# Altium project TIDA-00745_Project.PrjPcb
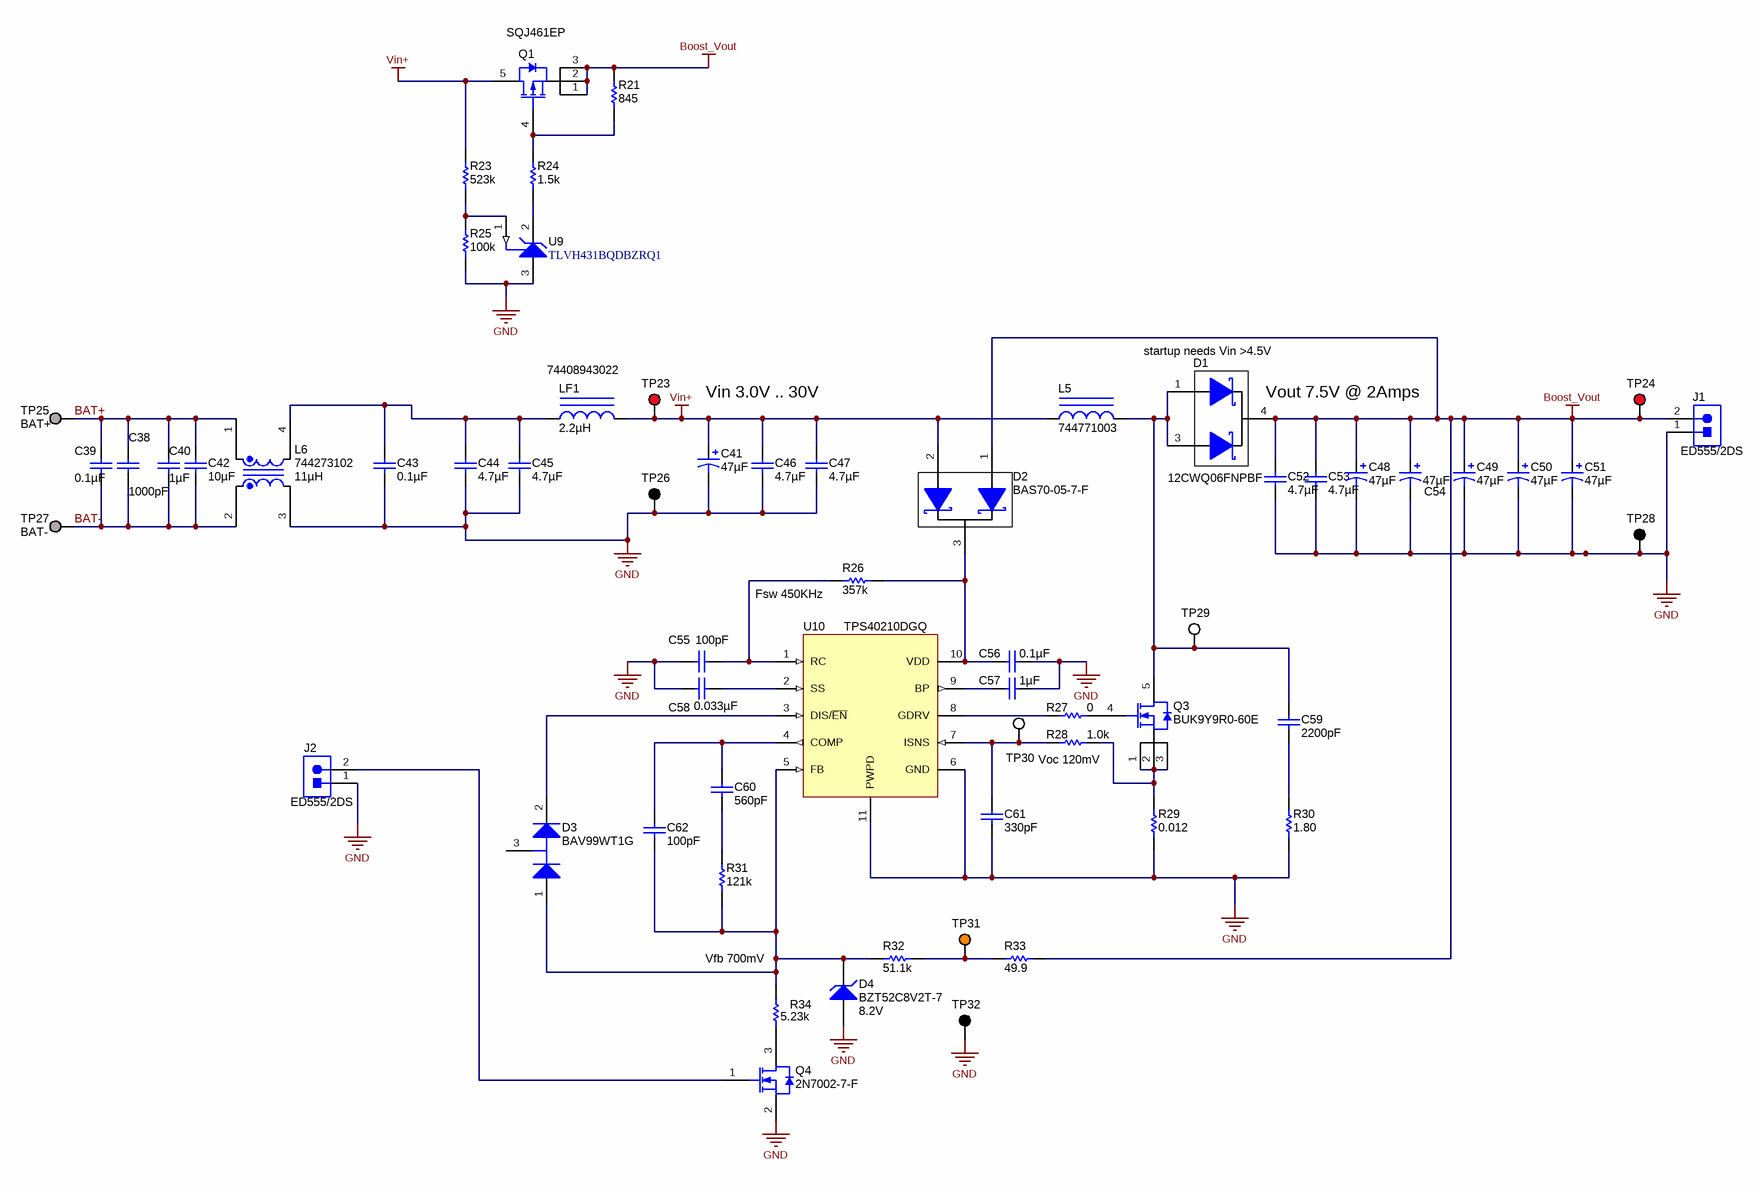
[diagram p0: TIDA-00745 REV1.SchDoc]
TechSupport: http://www.ti.com/support; SCH_Rev: E1; PRJ_Title: SMPS design for Automotive Body Contrl Module; PRJ_Number: TIDA-00745; PRJ_Engineer: Ambreesh Tripathi; PRJ_Customer: Public Release; PCB_Rev: E1; PCB_Layout: Dee Lim; CopyrightYear: 2015
3 sheets, 180 parts. Net scope: global (net labels, ports and power ports of the same name join across sheets).
Board file: TIDA-00745_PCB.PcbDoc
Sheets:
  TIDA-00745 REV1.SchDoc
  TIDA-00745_Hardware.SchDoc
  TIDA-00745_Buck REV1.SchDoc

## Sheet TIDA-00745 REV1.SchDoc
size 431 x 279 mm; Date: Not shown in title block; ApprovedBy: Not shown in title block; CheckedBy: Not shown in title block; Author: Not shown in title block; CompanyName: Not shown in title block; Engineer: Not shown in title block; Organization: Not shown in title block; Address1: Not shown in title block; Address2: Not shown in title block; Address3: Not shown in title block; Address4: Not shown in title block; DocumentNumber: 1; Revision: Use project parameter SCH_Rev; SheetNumber: 2; SheetTotal: 1; PageSetup: Record=PageOptions|CenterHorizontal=True|CenterVertical=True|PrintScale=0.64|XCorrection=1.00|YCorrection=1.00|PrintKind=0|BorderSize=5000000|LeftOffset=0|BottomOffset=0|Orientation=2|PaperLength=1000|PaperWidth=1000|Scale=100|PaperSource=15|PrintQuality=-3|MediaType=1|DitherType=10|PrintScaleMode=1|PaperKind=Tabloid (11 x 17")|PaperIndex=17

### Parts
C38  ValueDisplayed: 1000pF  [0603]  (hidden comment: 06031C102KAT2A)
C39  ValueDisplayed: 0.1µF  [0603]  (hidden comment: GRM188R72A104KA35D)
C40  ValueDisplayed: 1µF  [1206]  (hidden comment: C3216X7R2A105M160AA)
C41  ValueDisplayed: 47µF  [SM_RADIAL_G]  (hidden comment: EEE-FC1H470P)
C42  ValueDisplayed: 10µF  [1210]  (hidden comment: GRM32ER71H106KA12L)
C43  ValueDisplayed: 0.1µF  [0603]  (hidden comment: C1608X7R1H104K)
C44  ValueDisplayed: 4.7µF  [1206]  (hidden comment: GRM31CR71H475KA12L)
C45  ValueDisplayed: 4.7µF  [1206]  (hidden comment: GRM31CR71H475KA12L)
C46  ValueDisplayed: 4.7µF  [1210]  (hidden comment: GRM32ER71H475KA88L)
C47  ValueDisplayed: 4.7µF  [1210]  (hidden comment: GRM32ER71H475KA88L)
C48  ValueDisplayed: 47µF  [SM_RADIAL_G]  (hidden comment: EEE-FC1H470P)
C49  ValueDisplayed: 47µF  [SM_RADIAL_G]  (hidden comment: EEE-FC1H470P)
C50  ValueDisplayed: 47µF  [SM_RADIAL_G]  (hidden comment: EEE-FC1H470P)
C51  ValueDisplayed: 47µF  [SM_RADIAL_G]  (hidden comment: EEE-FC1H470P)
C52  ValueDisplayed: 4.7µF  [1210]  (hidden comment: GRM32ER71H475KA88L)
C53  ValueDisplayed: 4.7µF  [1210]  (hidden comment: GRM32ER71H475KA88L)
C54  ValueDisplayed: 47µF  [SM_RADIAL_G]  (hidden comment: EEE-FC1H470P)
C55  ValueDisplayed: 100pF  [0603]  (hidden comment: 06035A101JAT2A)
C56  ValueDisplayed: 0.1µF  [0603]  (hidden comment: GRM188R71H104KA93D)
C57  ValueDisplayed: 1µF  [0603]  (hidden comment: GRM188R71E105KA12D)
C58  ValueDisplayed: 0.033µF  [0603]  (hidden comment: GRM188R71H333KA61D)
C59  ValueDisplayed: 2200pF  [0603]  (hidden comment: GRM188R71E222KA01D)
C60  ValueDisplayed: 560pF  [0603]  (hidden comment: C0603C561K5RACTU)
C61  ValueDisplayed: 330pF  [0603]  (hidden comment: GRM188R71H331KA01D)
C62  ValueDisplayed: 100pF  [0603]  (hidden comment: 06035A101JAT2A)
D1  12CWQ06FNPBF  [DPAK]
D2  BAS70-05-7-F  [SOT-23]
D3  BAV99WT1G  [SOT-323]
D4  BZT52C8V2T-7  value 8.2V  [SOD-523]
J1  ED555/2DS  [TERM_BLK_ED555-2DS]
J2  ED555/2DS  [TERM_BLK_ED555-2DS]
L5  744771003  [WE-PD-L]
L6  744273102  ValueDisplayed: 11µH  [WE-SL5_HC]
LF1  74408943022  ValueDisplayed: 2.2µH  [WE-SPC_4838]
Q1  SQJ461EP  [PowerPAK_SO-8L]
Q3  BUK9Y9R0-60E  [LFPAK56]
Q4  2N7002-7-F  [SOT-23]
R21  ValueDisplayed: 845  [0603]  (hidden comment: CRCW0603845RFKEA)
R23  ValueDisplayed: 523k  [0603]  (hidden comment: CRCW0603523KFKEA)
R24  ValueDisplayed: 1.5k  [0603]  (hidden comment: CRCW06031K50JNEA)
R25  ValueDisplayed: 100k  [0603]  (hidden comment: CRCW0603100KFKEA)
R26  ValueDisplayed: 357k  [0603]  (hidden comment: RC0603FR-07357KL)
R27  value 0  [0603]  (hidden comment: CRCW06030000Z0EA)
R28  value 1.0k  [0603]  (hidden comment: CRCW06031K00JNEA)
R29  ValueDisplayed: 0.012  [1206]  (hidden comment: CSR1206FK12L0)
R30  value 1.80  [1206]  (hidden comment: RC1206FR-071R8L)
R31  ValueDisplayed: 121k  [0603]  (hidden comment: CRCW0603121KFKEA)
R32  ValueDisplayed: 51.1k  [0603]  (hidden comment: CRCW060351K1FKEA)
R33  value 49.9  [0603]  (hidden comment: CRCW060349R9FKEA)
R34  ValueDisplayed: 5.23k  [0603]  (hidden comment: CRCW06035K23FKEA)
TP23  5000  [Keystone5000]  (value not drawn)
TP24  5000  [Keystone5000]  (value not drawn)
TP25  BAT+  [Keystone1503-2]
TP26  5001  [Keystone5001]  (value not drawn)
TP27  BAT-  [Keystone1503-2]
TP28  5001  [Keystone5001]  (value not drawn)
TP29  5002  [Keystone5002]  (value not drawn)
TP30  5002  [Keystone5002]  (value not drawn)
TP31  5003  [Keystone5003]  (value not drawn)
TP32  5001  [Keystone5001]  (value not drawn)
U9  TLVH431BQDBZRQ1  [DBZ0003A_N]
U10  TPS40210DGQ  [DGQ0010D_N]

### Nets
Boost_Vout: C48.1(+) C49.1(+) C50.1(+) C51.1(+) C52.1 C53.1 C54.1(+) D1.4(K) D2.1(A) J1.2 Q1.1(S) Q1.2(S) Q1.3(S) R21.2 R33.2 TP24.1  [project net Vs]
GND: C41.2(-) C43.2 C44.2 C45.2 C46.2 C47.2 C48.2(-) C49.2(-) C50.2(-) C51.2(-) C52.2 C53.2 C54.2(-) C55.1 C56.2 C57.2 C58.2 C61.2 D4.2(A) J1.1 J2.1 L6.3 Q4.2(S) R25.1 R29.1 R30.1 TP26.1 TP28.1 TP32.1 U9.3(ANODE) U10.6(GND) U10.11(PWPD)
Vin+: C41.1(+) C46.1 C47.1 D2.2(A) L5.1 LF1.2 Q1.5(D) R23.2 TP23.1
BAT+: C38.1 C39.1 C40.1 C42.1 L6.1 TP25.1
BAT-: C38.2 C39.2 C40.2 C42.2 L6.2 TP27.1
NetC43_1: C43.1 C44.1 C45.1 L6.4 LF1.1
NetC55_2: C55.2 R26.1 U10.1(RC)
NetC56_1: C56.1 D2.3(K) R26.2 U10.10(VDD)
NetC57_1: C57.1 U10.9(BP)
NetC58_1: C58.1 U10.2(SS)
NetC59_1: C59.1 D1.1(A) D1.3(A) L5.2 Q3.5(D) TP29.1
NetC59_2: C59.2 R30.2
NetC60_1: C60.1 C62.2 U10.4(COMP)
NetC60_2: C60.2 R31.2
NetC61_1: C61.1 R28.1 TP30.1 U10.7(ISNS)
NetC62_1: C62.1 D3.1(A) D4.1(K) R31.1 R32.1 R34.2 U10.5(FB)
NetD3_2: D3.2(K) U10.3(DIS/~{EN})
NetJ2_2: J2.2 Q4.1(G)
NetQ1_4: Q1.4(G) R21.1 R24.2
NetQ3_1: Q3.1(S) Q3.2(S) Q3.3(S) R28.2 R29.2
NetQ3_4: Q3.4(G) R27.2
NetQ4_3: Q4.3(D) R34.1
NetR23_1: R23.1 R25.2 U9.1(REF)
NetR24_1: R24.1 U9.2(CATHODE)
NetR27_1: R27.1 U10.8(GDRV)
NetR32_2: R32.2 R33.1 TP31.1

Not connected (* = marked no-connect by the designer): D3 3(C)

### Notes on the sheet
- (near D1) startup needs Vin >4.5V
- Vin 3.0V .. 30V
- (near D1) Vout 7.5V @ 2Amps
- (near R26) Fsw 450KHz
- (near R28) Voc 120mV
- (near R34) Vfb 700mV

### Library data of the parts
C38 = 06031C102KAT2A: CAP, CERM, 1000 pF, 100 V, +/- 10%, X7R, 0603; Manufacturer: AVX; Polarized: N; CompType: Capacitor; Value: 1000pF; U/M: EA; Cap_F: 0.000000001; Tolerance_%: 10; ESR_ohm: 0.276; Value1: 0.276 ohm; VDC_V: 100; Value2: 100V; TaMin_C: -55; TaMax_C: 125
C39 = GRM188R72A104KA35D: CAP, CERM, 0.1uF, 100V, +/-10%, X7R, 0603; Manufacturer: MuRata; Polarized: N; CompType: Capacitor; U/M: EA; Cap_F: 0.0000001; Tolerance_%: 10; Value1: Unknown; VDC_V: 100; TaMin_C: -55; TaMax_C: 125
C40 = C3216X7R2A105M160AA: CAP, CERM, 1uF, 100V, +/-20%, X7R, 1206; Manufacturer: TDK; Polarized: N; CompType: Capacitor; U/M: EA; Cap_F: 0.000001; Tolerance_%: 20; Value1: Unknown; VDC_V: 100; TaMin_C: -55; TaMax_C: 125
C41 C48-C51 C54 = EEE-FC1H470P: CAP, AL, 47 µF, 50 V, +/- 20%, 0.3 ohm, SMD; Manufacturer: Panasonic; Polarized: Y; CompType: Capacitor; Value: 47uF; U/M: EA; Cap_F: 0.000047; Tolerance_%: 20; Value1: 0.3 ohm; VDC_V: 50; Value2: 50V; ESR_ohm: 0.3; IRMS_A: 0.5; TaMin_C: -40; TaMax_C: 105; Cap_Case: G
C42 = GRM32ER71H106KA12L: CAP, CERM, 10uF, 50V, +/-10%, X7R, 1210; Manufacturer: MuRata; Polarized: N; CompType: Capacitor; U/M: EA; Cap_F: 0.00001; Tolerance_%: 10; Value1: Unknown; VDC_V: 50; TaMin_C: -55; TaMax_C: 125
C43 = C1608X7R1H104K: CAP, CERM, 0.1uF, 50V, +/-10%, X7R, 0603; Manufacturer: TDK; Polarized: N; CompType: Capacitor; U/M: EA; Cap_F: 0.0000001; Tolerance_%: 10; ESR_Ohm: 0.017; Value1: 0.017 ohm; VDC_V: 50; TaMin_C: -55; TaMax_C: 125
C44 C45 = GRM31CR71H475KA12L: CAP, CERM, 4.7uF, 50V, +/-10%, X7R, 1206; Manufacturer: MuRata; Polarized: N; CompType: Capacitor; U/M: EA; Cap_F: 0.0000047; Tolerance_%: 10; Value1: Unknown; VDC_V: 50; TaMin_C: -55; TaMax_C: 125; Cap_Case: 2220
C46 C47 C52 C53 = GRM32ER71H475KA88L: CAP, CERM, 4.7 µF, 50 V, +/- 10%, X7R, 1210; Manufacturer: MuRata; Polarized: N; CompType: Capacitor; Value: 4.7uF; U/M: EA; Cap_F: 0.0000047; Tolerance_%: 10; ESR_ohm: 0.002; Value1: 0.002 ohm; VDC_V: 50; Value2: 50V; TaMin_C: -55; TaMax_C: 125
C55 C62 = 06035A101JAT2A: CAP, CERM, 100 pF, 50 V, +/- 5%, C0G/NP0, 0603; Manufacturer: AVX; Polarized: N; CompType: Capacitor; Value: 100pF; U/M: EA; Cap_F: 0.0000000001; Tolerance_%: 5; ESR_ohm: 0.119; Value1: 0.119 ohm; VDC_V: 50; Value2: 50V; TaMin_C: -55; TaMax_C: 125; AEC Category: Q200
C56 = GRM188R71H104KA93D: CAP, CERM, 0.1uF, 50V, +/-10%, X7R, 0603; Manufacturer: MuRata; Polarized: N; CompType: Capacitor; U/M: EA; Cap_F: 0.0000001; Tolerance_%: 10; Value1: Unknown; VDC_V: 50; TaMin_C: -55; TaMax_C: 125
C57 = GRM188R71E105KA12D: CAP, CERM, 1uF, 25V, +/-10%, X7R, 0603; Manufacturer: MuRata; Polarized: N; CompType: Capacitor; U/M: EA; Cap_F: 0.000001; Tolerance_%: 10; Value1: Unknown; VDC_V: 25; TaMin_C: -55; TaMax_C: 125
C58 = GRM188R71H333KA61D: CAP, CERM, 0.033 µF, 50 V, +/- 10%, X7R, 0603; Manufacturer: MuRata; Polarized: N; CompType: Capacitor; Value: 0.033uF; U/M: EA; Cap_F: 0.000000033; Tolerance_%: 10; Value1: Unknown; VDC_V: 50; Value2: 50V; TaMin_C: -55; TaMax_C: 125
C59 = GRM188R71E222KA01D: CAP, CERM, 2200pF, 25V, +/-10%, X7R, 0603; Manufacturer: MuRata; Polarized: N; CompType: Capacitor; U/M: EA; Cap_F: 0.0000000022; Tolerance_%: 10; Value1: Unknown; VDC_V: 25; TaMin_C: -55; TaMax_C: 125
C60 = C0603C561K5RACTU: CAP, CERM, 560 pF, 50 V, +/- 10%, X7R, 0603; Manufacturer: Kemet; Polarized: N; CompType: Capacitor; Value: 560pF; U/M: EA; Cap_F: 0.00000000056; Tolerance_%: 10; Value1: Unknown; VDC_V: 50; Value2: 50V; TaMin_C: -55; TaMax_C: 125
C61 = GRM188R71H331KA01D: CAP, CERM, 330pF, 50V, +/-10%, X7R, 0603; Manufacturer: MuRata; Polarized: N; CompType: Capacitor; U/M: EA; Cap_F: 0.00000000033; Tolerance_%: 10; Value1: Unknown; VDC_V: 50; TaMin_C: -55; TaMax_C: 125
D1 = 12CWQ06FNPBF: Diode, Schottky, 60 V, 12 A, DPAK; Manufacturer: Vishay-Semiconductor; U/M: EA; Vf_V: 0.79; Value: 60V; Value1: 12A; Value2: 0.79V; Io_A: 12; Vr_V: 60; TJmax_C: 150; RJC_CperW: 1.5
D2 = BAS70-05-7-F: Diode, Schottky, 70 V, 0.07 A, SOT-23; Manufacturer: Diodes Inc.; SymbolCreator: a0412235; U/M: EA; Vf_V: 1.7; Value: 70V; Value1: 0.07A; Value2: 1.7V; Io_A: 0.07; Vr_V: 70
D3 = BAV99WT1G: Diode, P-N, 70 V, 0.2 A, SOT-323; Manufacturer: Fairchild Semiconductor; U/M: EA; Vf_V: 0.63; Value: 70V; Value1: 0.2A; Value2: 0.63V; Io_A: 0.2; Vr_V: 70; TJmax_C: 150
D4 = BZT52C8V2T-7: Diode, Zener, 8.2 V, 300 mW, SOD-523; Manufacturer: Diodes Inc.; SymbolCreator: a0412235; U/M: EA; Power_W: 0.3; Vz_V: 8.2; Value1: 0.3W; RJA_CperW: 417
J1 J2 = ED555/2DS: Terminal Block, 6A, 3.5mm Pitch, 2-Pos, TH; Manufacturer: On-Shore Technology; SymbolCreator: a0412235; CompType: Connector; U/M: EA
L5 = 744771003: Inductor, Shielded Drum Core, Ferrite, 3.5 µH, 9 A, 0.005 ohm, SMD; Manufacturer: Wurth Elektronik; Value: 3.5uH; Ind_H: 3.5E-6; ValueDisplayed: 3.5µH; Imax_A: 9; Irms: 9.25A @ 40C rise; Isat: 9A @ 10% inductance drop; DCR_ohm: 0.005; Value2: 9A
L6 = 744273102: Coupled inductor, 11 µH, 2.5 A, 0.03 ohm, SMD; Manufacturer: Wurth Elektronik eiSos; SymbolCreator: a0799628; Ind_H: 11.0E-6; DCR_ohm: 0.03; Isat: 2.5; Value: 11uH
LF1 = 74408943022: Inductor, Shielded Drum Core, Ferrite, 2.2 µH, 3 A, 0.026 ohm, SMD; Manufacturer: Wurth Elektronik; Value: 2.2uH; Ind_H: 2.2E-6; Imax_A: 3; Irms: 3A @ 40C rise; Isat: 4.6A @ 35% inductance drop; DCR_ohm: 0.026; Value2: 3A; AEC Category: Q200
Q1 = SQJ461EP: MOSFET, P-CH, -60 V, 30 A, PowerPAK_SO-8L; Manufacturer: Vishay-Siliconix; Alternate Manufacturer: None; SymbolCreator: a0411947; U/M: EA; ChType: P; Value: -60V; Value1: 0.031 ohm; Rdson45_ohm: 0.031; Value2: 90 nC; QgTyp_nC: 90; Vgs_V: 20; IdsMax_A: 30
Q3 = BUK9Y3R5-40E,115: MOSFET, N-CH, 60 V, 100 A, SOT669; Manufacturer: NXP Semiconductor; Alternate Manufacturer: None; SymbolCreator: a0412235; U/M: EA; ChType: N; Value: 40V; VdsMax_V: 40; Value1: ? ohm; Value2: 30.2 nC; QgTyp_nC: 30.2; Vgs_V: 10; IdsMax_A: 100
Q4 = 2N7002-7-F: MOSFET, N-CH, 60 V, 0.17 A, SOT-23; Manufacturer: Diodes Inc.; Alternate Manufacturer: None; U/M: EA; ChType: N; Value: 60V; VdsMax_V: 60; Value1: 7.5 ohm; Rdson45_ohm: 7.5; Value2: 223 nC; QgTyp_nC: 223; Vgs_V: 20; IdsMax_A: 0.17
R21 = CRCW0603845RFKEA: RES, 845, 1%, 0.1 W, 0603; Manufacturer: Vishay-Dale; CompType: Resistor; Value: 845; Value_Code: 845R; Tolerance_%: 1; Power_W: 0.1; Value2: 0.1W; VDC_V: 75; TempCo: 100 ppm/C; EIA_Code: E96; U/M: EA
R23 = CRCW0603523KFKEA: RES, 523 k, 1%, 0.1 W, 0603; Manufacturer: Vishay-Dale; CompType: Resistor; Value: 523k; Res_ohm: 523000; Tolerance_%: 1; Power_W: 0.1; Value2: 0.1W; VDC_V: 75; TempCo: 100 ppm/C; EIA_Code: E96; U/M: EA
R24 = CRCW06031K50JNEA: RES, 1.5 k, 5%, 0.1 W, 0603; Manufacturer: Vishay-Dale; CompType: Resistor; Value: 1.5k; Res_ohm: 1500; Value_Code: 1k50; Tolerance_%: 5; Power_W: 0.1; Value2: 0.1W; VDC_V: 75; TempCo: 200 ppm/C; EIA_Code: E24; U/M: EA
R25 = CRCW0603100KFKEA: RES, 100 k, 1%, 0.1 W, 0603; Manufacturer: Vishay-Dale; CompType: Resistor; Value: 100k; Res_ohm: 100000; Tolerance_%: 1; Power_W: 0.1; Value2: 0.1W; VDC_V: 75; TempCo: 100 ppm/C; EIA_Code: E96; U/M: EA
R26 = RC0603FR-07357KL: RES, 357 k, 1%, 0.1 W, 0603; Manufacturer: Yageo America; CompType: Resistor; Value: 357k; Res_ohm: 357000; Tolerance_%: 1; Power_W: 0.1; Value2: 0.1W; VDC_V: 150; TempCo: 200 ppm/C; EIA_Code: E96; U/M: EA
R27 = CRCW06030000Z0EA: RES, 0 ohm, 5%, 0.1W, 0603; Manufacturer: Vishay-Dale; CompType: Resistor; Value_Code: 0000; Tolerance_%: 5; Power_W: 0.1; VDC_V: 75; TempCo: 200 ppm/C; EIA_Code: E24; U/M: EA
R28 = CRCW06031K00JNEA: RES, 1.0k ohm, 5%, 0.1W, 0603; Manufacturer: Vishay-Dale; CompType: Resistor; Res_ohm: 1000; Value_Code: 1k00; Tolerance_%: 5; Power_W: 0.1; VDC_V: 75; TempCo: 200 ppm/C; EIA_Code: E24; U/M: EA
R29 = CSR1206FK12L0: RES, 0.012, 1%, 0.5 W, 1206; Manufacturer: Stackpole Electronics Inc; CompType: Resistor; Value: 0.012; Value_Code: R012; Tolerance_%: 1; Power_W: 0.5; Value2: 0.5W; TempCo: 100 ppm/C; EIA_Code: E96; U/M: EA
R30 = RC1206FR-071R8L: RES, 1.80 ohm, 1%, 0.25W, 1206; Manufacturer: Yageo America; CompType: Resistor; Res_ohm: 1.8; Value_Code: 1R80; Tolerance_%: 1; Power_W: 0.25; VDC_V: 200; TempCo: 200 ppm/C; U/M: EA
R31 = CRCW0603121KFKEA: RES, 121 k, 1%, 0.1 W, 0603; Manufacturer: Vishay-Dale; CompType: Resistor; Value: 121k; Res_ohm: 121000; Tolerance_%: 1; Power_W: 0.1; Value2: 0.1W; VDC_V: 75; TempCo: 100 ppm/C; EIA_Code: E96; U/M: EA
R32 = CRCW060351K1FKEA: RES, 51.1 k, 1%, 0.1 W, 0603; Manufacturer: Vishay-Dale; CompType: Resistor; Value: 51.1k; Res_ohm: 51100; Value_Code: 51k1; Tolerance_%: 1; Power_W: 0.1; Value2: 0.1W; VDC_V: 75; TempCo: 100 ppm/C; EIA_Code: E96; U/M: EA
R33 = CRCW060349R9FKEA: RES, 49.9 ohm, 1%, 0.1W, 0603; Manufacturer: Vishay-Dale; CompType: Resistor; Value_Code: 49R9; Tolerance_%: 1; Power_W: 0.1; VDC_V: 75; TempCo: 100 ppm/C; EIA_Code: E96; U/M: EA
R34 = CRCW06035K23FKEA: RES, 5.23 k, 1%, 0.1 W, 0603; Manufacturer: Vishay-Dale; CompType: Resistor; Value: 5.23k; Res_ohm: 5230; Value_Code: 5k23; Tolerance_%: 1; Power_W: 0.1; Value2: 0.1W; VDC_V: 75; TempCo: 100 ppm/C; EIA_Code: E96; U/M: EA
TP23 TP24 = 5000: Test Point, Miniature, Red, TH; Manufacturer: Keystone; CompType: Test Point Loop; U/M: EA
TP25 TP27 = 1503-2: Terminal, Turret, TH, Double; Manufacturer: Keystone; CompType: Turret Terminal; U/M: EA
TP26 TP28 TP32 = 5001: Test Point, Miniature, Black, TH; Manufacturer: Keystone; CompType: Test Point Loop; U/M: EA
TP29 TP30 = 5002: Test Point, Miniature, White, TH; Manufacturer: Keystone; CompType: Test Point Loop; U/M: EA
TP31 = 5003: Test Point, Miniature, Orange, TH; Manufacturer: Keystone; CompType: Test Point Loop; U/M: EA
U9 = TLVH431BQDBZRQ1: Automotive Catalog Low-Voltage Adjustable Precision Shunt Regulator, 80 mA, -40 to 125 degC, 3-pin SOT-23 (DBZ), Green (RoHS & no Sb/Br); Manufacturer: Texas Instruments; Alternate PartNumber: Equivalent; Initial Accuracy @ 25/deg C(%): 0.5; Iout/Iz(Max)(mA): 80; SubFamily: Shunt Voltage Reference; VO Adj(Max)(V): 18; VO Adj(Min)(V): 1.24
U10 = TPS40210DGQ: 4.5-V TO 52-V INPUT CURRENT MODE BOOST CONTROLLER, DGQ0010D; Alternate Manufacturer: None; Manufacturer: Texas Instruments; SymbolCreator: a0412235; CompType: IC; U/M: EA

## Sheet TIDA-00745_Hardware.SchDoc
size 431 x 279 mm; Date: Not shown in title block; ApprovedBy: Not shown in title block; CheckedBy: Not shown in title block; Author: Not shown in title block; CompanyName: Not shown in title block; Engineer: Not shown in title block; Organization: Not shown in title block; Address1: Not shown in title block; Address2: Not shown in title block; Address3: Not shown in title block; Address4: Not shown in title block; DocumentNumber: 1; Revision: Use project parameter SCH_Rev; SheetNumber: 4; SheetTotal: 1; PageSetup: Record=PageOptions¦CenterHorizontal=True¦CenterVertical=True¦PrintScale=1.00¦XCorrection=1.00¦YCorrection=1.00¦PrintKind=0¦BorderSize=5000000¦LeftOffset=0¦BottomOffset=0¦Orientation=2¦PaperLength=1000¦PaperWidth=1000¦Scale=100¦PaperSource=15¦PrintQuality=600¦MediaType=1¦DitherType=10¦PaperKind=Letter¦PrintScaleMode=1
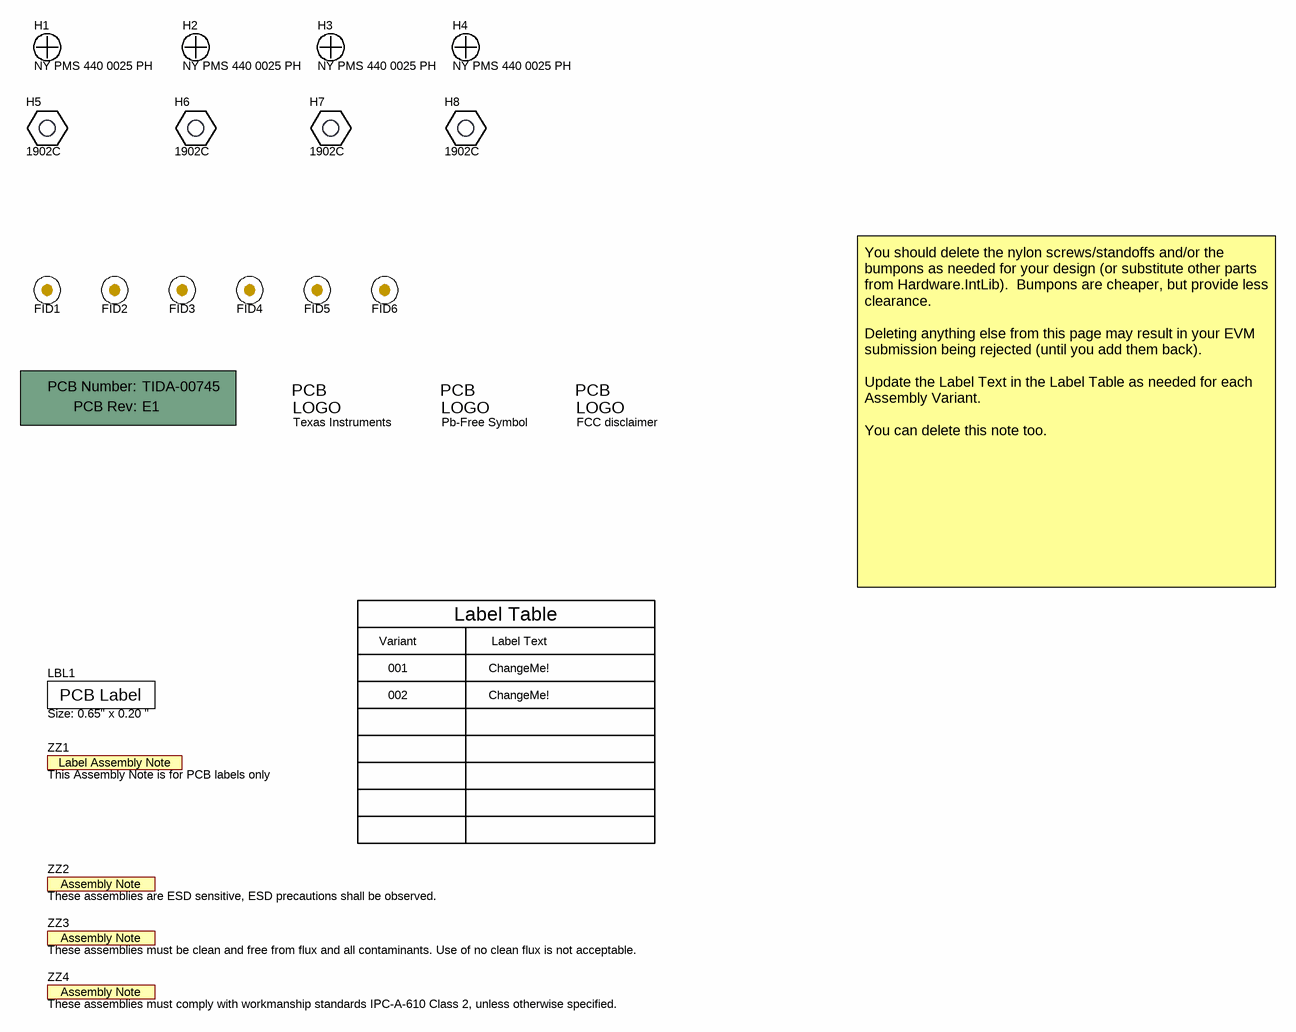
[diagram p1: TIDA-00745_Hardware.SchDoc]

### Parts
!PCB1  Printed Circuit Board  (value not drawn)  (mechanical)
FID1  Fiducial  [Fiducial10-20]  (value not drawn)
FID2  Fiducial  [Fiducial10-20]  (value not drawn)
FID3  Fiducial  [Fiducial10-20]  (value not drawn)
FID4  Fiducial  [Fiducial10-20]  (value not drawn)
FID5  Fiducial  [Fiducial10-20]  (value not drawn)
FID6  Fiducial  [Fiducial10-20]  (value not drawn)
H1  NY PMS 440 0025 PH  [NY PMS 440 0025 PH]
H2  NY PMS 440 0025 PH  [NY PMS 440 0025 PH]
H3  NY PMS 440 0025 PH  [NY PMS 440 0025 PH]
H4  NY PMS 440 0025 PH  [NY PMS 440 0025 PH]
H5  1902C  [Keystone_1902C]
H6  1902C  [Keystone_1902C]
H7  1902C  [Keystone_1902C]
H8  1902C  [Keystone_1902C]
LBL1  Size: 0.65" x 0.20 "  [Label_650x200]
Logo1  Texas Instruments  [TI_Horizontal_Overlay_Medium]  (no BOM)
Logo2  Pb-Free Symbol  [Pb-Free_Overlay_Small]  (no BOM)
Logo3  FCC disclaimer  [FCC_disclaimer]  (no BOM)
ZZ1  This Assembly Note is for PCB labels only  [AssemblyNoteLabel]  (no BOM)
ZZ2  These assemblies are ESD sensitive, ESD precautions shall be observed.  [AssemblyNote]  (no BOM)
ZZ3  These assemblies must be clean and free from flux and all contaminants. Use of no clean flux is not acceptable.  [AssemblyNote]  (no BOM)
ZZ4  These assemblies must comply with workmanship standards IPC-A-610 Class 2, unless otherwise specified.  [AssemblyNote]  (no BOM)

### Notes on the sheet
- Variant
- Label Table
- Label Text
- You should delete the nylon screws/standoffs and/or the bumpons as needed for your design (or substitute other parts from Hardware.IntLib).  Bumpons are cheaper, but provide less clearance.
  Deleting anything else from this page may result in your EVM submission being rejected (until you add them back).
  Update the Label Text in the Label Table as needed for each Assembly Variant.
  You can delete this note too.
- 001
- 002
- ChangeMe!

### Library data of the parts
!PCB1 = PCB: Manufacturer: Any; PartNumber: TIDA-00745; SymbolCreator: a0412235
FID1-FID6 = Fiducial: Fiducial mark.  There is nothing to buy or mount.; SymbolCreator: codlsc
H1-H4 = NY PMS 440 0025 PH: Machine Screw, Round, #4-40 x 1/4, Nylon, Philips panhead; Manufacturer: B&F Fastener Supply; CompType: Hardware; SymbolCreator: codlsc; U/M: EA
H5-H8 = 1902C: Standoff, Hex, 0.5"L #4-40 Nylon; Manufacturer: Keystone; CompType: Hardware; SymbolCreator: a0412235
LBL1 = THT-14-423-10: Thermal Transfer Printable Labels, 0.650" W x 0.200" H - 10,000 per roll; Manufacturer: Brady; SymbolCreator: a0412235; CompType: Label
Logo1 = TI_Logo: Texas Instrument Corporate Signature; SymbolCreator: a0412235
Logo2 = Pb-Free: SymbolCreator: a0412235
Logo3 = FCC_disclaimer: SymbolCreator: codlsc
ZZ1 = AssemblyNoteLabel: SymbolCreator: a0412235
ZZ2-ZZ4 = AssemblyNote: SymbolCreator: codlsc

## Sheet TIDA-00745_Buck REV1.SchDoc
size 431 x 279 mm; Date: Not shown in title block; ApprovedBy: Not shown in title block; CheckedBy: Not shown in title block; Author: Not shown in title block; CompanyName: Not shown in title block; Engineer: Not shown in title block; Organization: Not shown in title block; Address1: Not shown in title block; Address2: Not shown in title block; Address3: Not shown in title block; Address4: Not shown in title block; DocumentNumber: 1; Revision: Use project parameter SCH_Rev; SheetNumber: 3; SheetTotal: 1; PageSetup: Record=PageOptions¦CenterHorizontal=True¦CenterVertical=True¦PrintScale=0.96¦XCorrection=1.00¦YCorrection=1.00¦PrintKind=0¦BorderSize=5000000¦LeftOffset=0¦BottomOffset=0¦Orientation=2¦PaperLength=1000¦PaperWidth=1000¦Scale=100¦PaperSource=15¦PrintQuality=-3¦MediaType=1¦DitherType=10¦PrintScaleMode=1¦PaperKind=Tabloid (11 x 17")¦PaperIndex=17
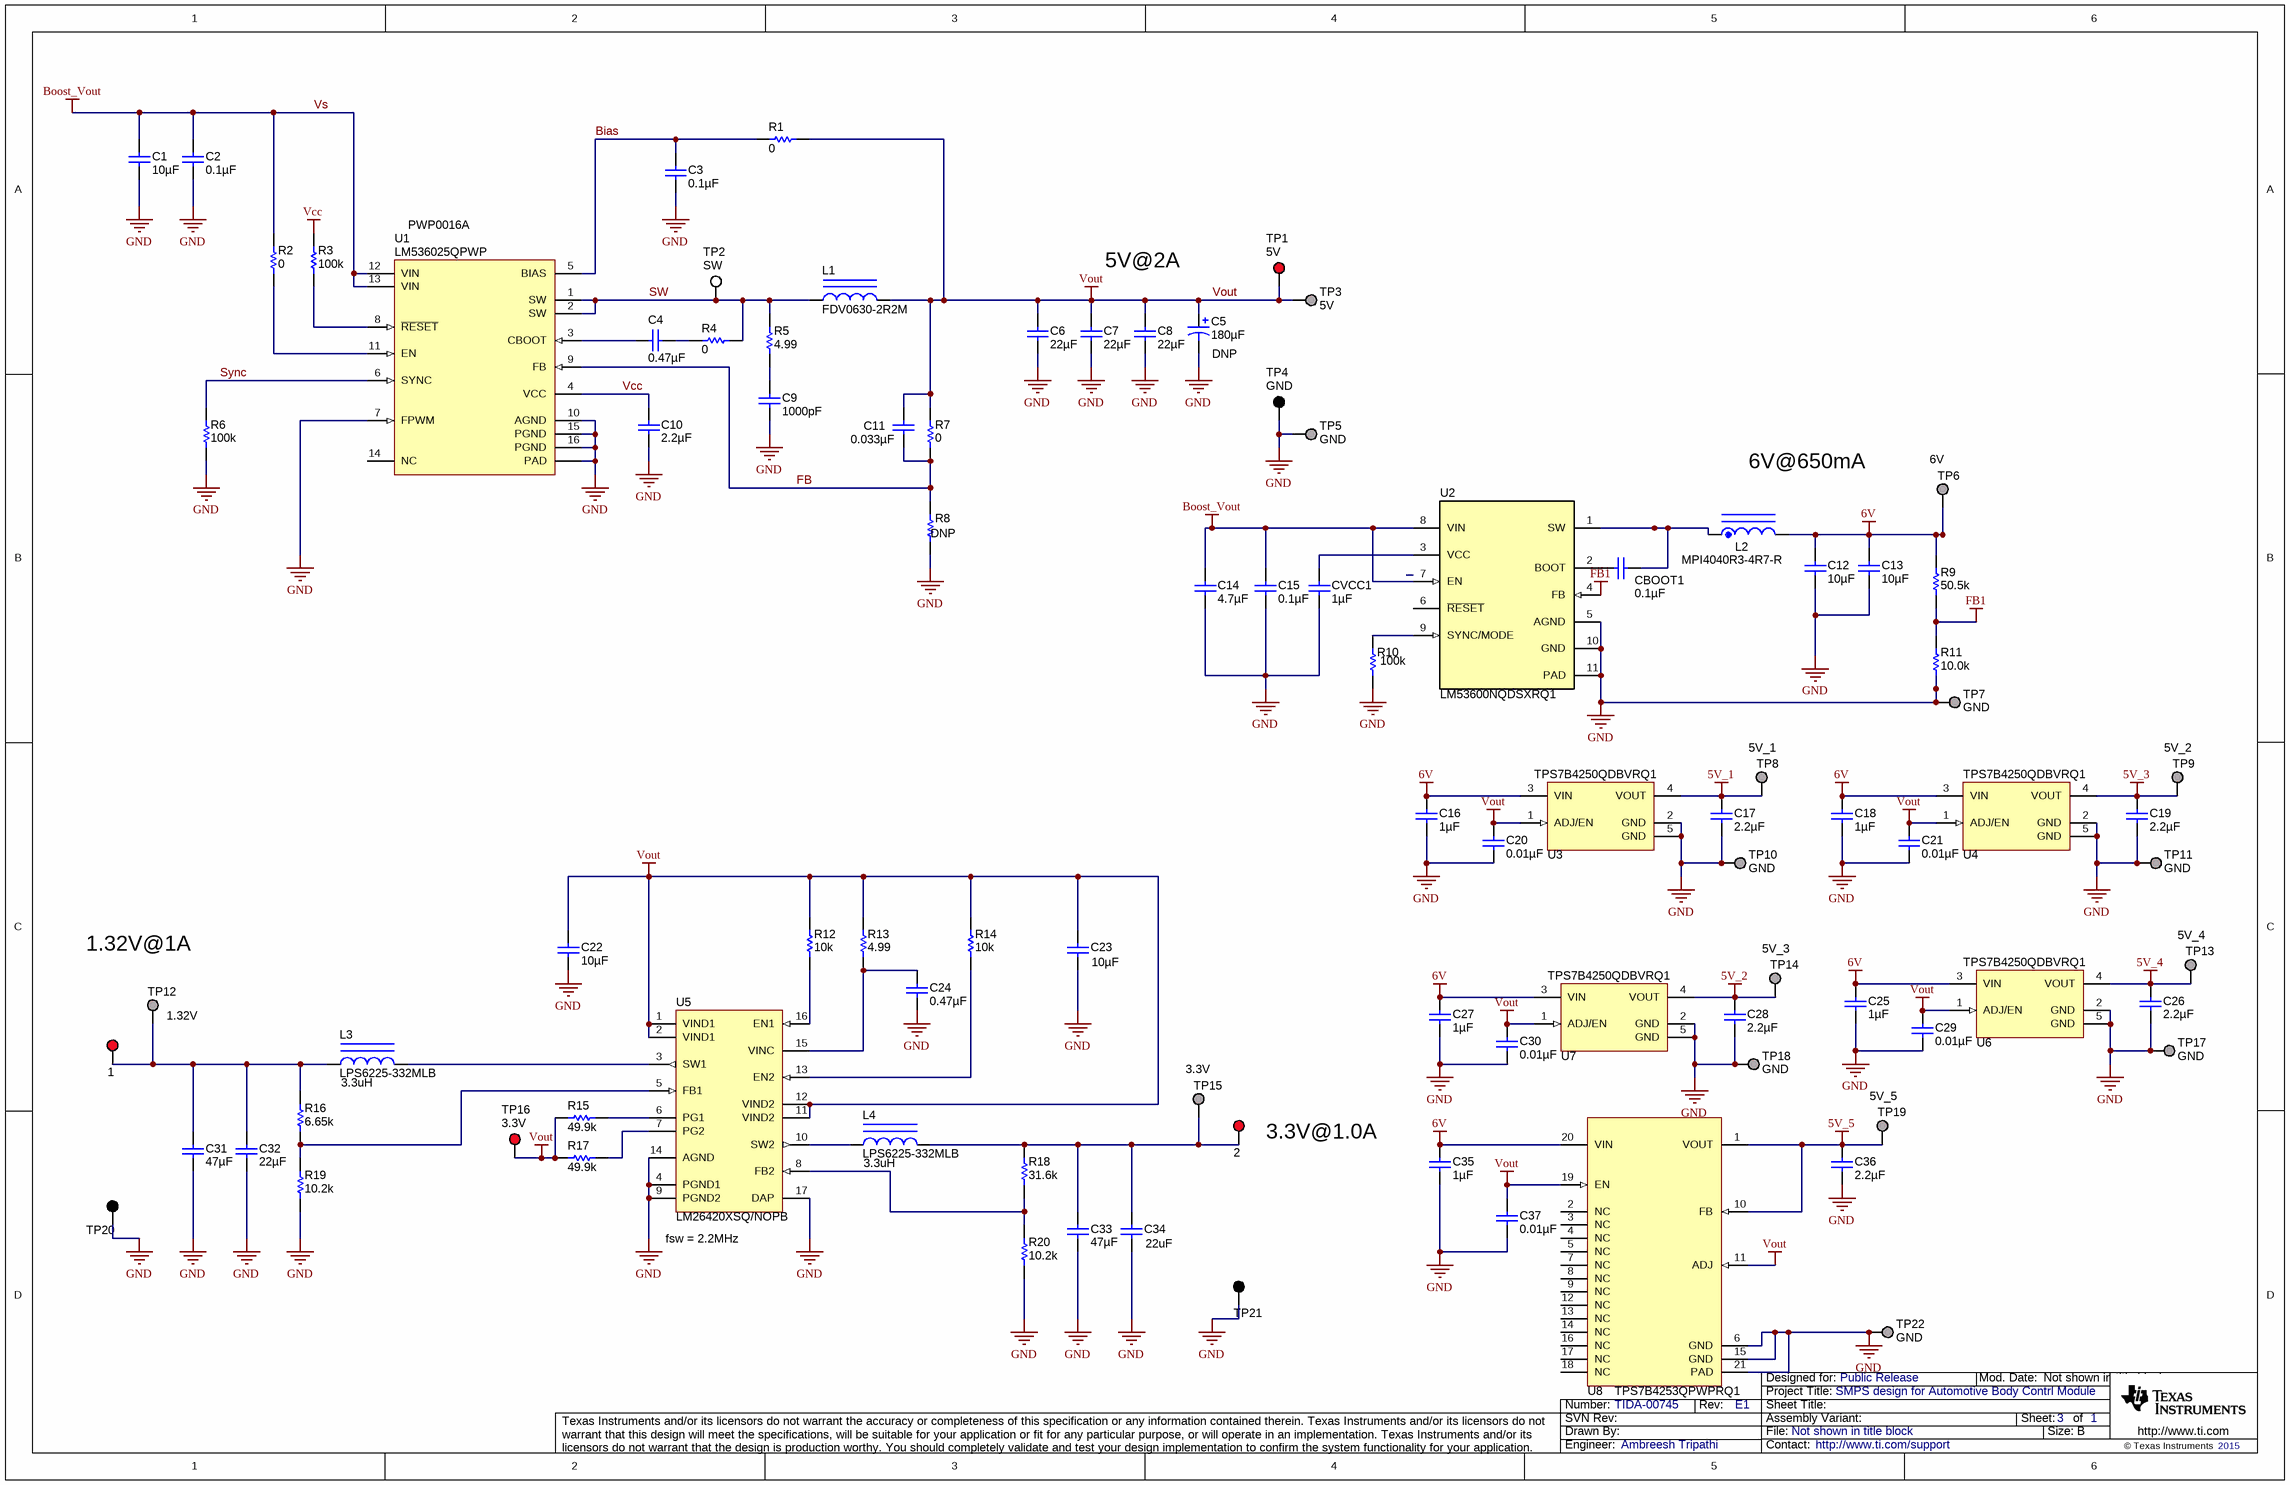
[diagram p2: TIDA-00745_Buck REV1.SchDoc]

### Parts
1  5010  [Keystone5010]  (value not drawn)
2  5010  [Keystone5010]  (value not drawn)
C1  ValueDisplayed: 10µF  [1210]  (hidden comment: GRM32ER71H106KA12L)
C2  ValueDisplayed: 0.1µF  [0603]  (hidden comment: 06035C104KAT2A)
C3  ValueDisplayed: 0.1µF  [0603]  (hidden comment: 06035C104KAT2A)
C4  ValueDisplayed: 0.47µF  [0603]  (hidden comment: C0603C474K8RACTU)
C5  ValueDisplayed: 180µF  [CAPSMT_62_F60]  (hidden comment: APXC6R3ARA181MF60G)
C6  ValueDisplayed: 22µF  [1210]  (hidden comment: C3225X7R1C226M)
C7  ValueDisplayed: 22µF  [1210]  (hidden comment: C3225X7R1C226M)
C8  ValueDisplayed: 22µF  [1210]  (hidden comment: C3225X7R1C226M)
C9  ValueDisplayed: 1000pF  [0603]  (hidden comment: 06031C102JAT2A)
C10  ValueDisplayed: 2.2µF  [0603]  (hidden comment: GRM188R71A225KE15D)
C11  ValueDisplayed: 0.033µF  [0603]  (hidden comment: GRM188R71E333KA01D)
C12  ValueDisplayed: 10µF  [0805_HV]  (hidden comment: C2012X7R1A106K125AC)
C13  ValueDisplayed: 10µF  [0805_HV]  (hidden comment: C2012X7R1A106K125AC)
C14  ValueDisplayed: 4.7µF  [0603]  (hidden comment: GRM188R61C475KAAJ)
C15  ValueDisplayed: 0.1µF  [0603]  (hidden comment: 0603YC104JAT2A)
C16  ValueDisplayed: 1µF  [0603]  (hidden comment: GRM188R71A105KA61D)
C17  ValueDisplayed: 2.2µF  [0603]  (hidden comment: GRM188R71A225KE15D)
C18  ValueDisplayed: 1µF  [0603]  (hidden comment: GRM188R71A105KA61D)
C19  ValueDisplayed: 2.2µF  [0603]  (hidden comment: GRM188R71A225KE15D)
C20  ValueDisplayed: 0.01µF  [0603]  (hidden comment: 0603ZC103KAT2A)
C21  ValueDisplayed: 0.01µF  [0603]  (hidden comment: 0603ZC103KAT2A)
C22  ValueDisplayed: 10µF  [1206]  (hidden comment: GRM31CR71A106KA01L)
C23  ValueDisplayed: 10µF  [1206]  (hidden comment: GRM31CR71A106KA01L)
C24  ValueDisplayed: 0.47µF  [0603]  (hidden comment: GRM188R71A474KA61D)
C25  ValueDisplayed: 1µF  [0603]  (hidden comment: GRM188R71A105KA61D)
C26  ValueDisplayed: 2.2µF  [0603]  (hidden comment: GRM188R71A225KE15D)
C27  ValueDisplayed: 1µF  [0603]  (hidden comment: GRM188R71A105KA61D)
C28  ValueDisplayed: 2.2µF  [0603]  (hidden comment: GRM188R71A225KE15D)
C29  ValueDisplayed: 0.01µF  [0603]  (hidden comment: 0603ZC103KAT2A)
C30  ValueDisplayed: 0.01µF  [0603]  (hidden comment: 0603ZC103KAT2A)
C31  ValueDisplayed: 47µF  [1206]  (hidden comment: GRM31CR60J476ME19L)
C32  ValueDisplayed: 22µF  [1206]  (hidden comment: GRM31CR71A226KE15L)
C33  ValueDisplayed: 47µF  [1206]  (hidden comment: GRM31CR60J476ME19L)
C34  value 22uF  [1206]  (hidden comment: GRM31CR71A226KE15L)
C35  ValueDisplayed: 1µF  [0603]  (hidden comment: GRM188R71A105KA61D)
C36  ValueDisplayed: 2.2µF  [0603]  (hidden comment: GRM188R71A225KE15D)
C37  ValueDisplayed: 0.01µF  [0603]  (hidden comment: 0603ZC103KAT2A)
CBOOT1  ValueDisplayed: 0.1µF  [0603]  (hidden comment: GRM188R71H104KA93D)
CVCC1  ValueDisplayed: 1µF  [0603]  (hidden comment: C1608X7R1C105K)
L1  FDV0630-2R2M  [IND_FDV0630]
L2  MPI4040R3-4R7-R  [MPI4040R3]
L3  LPS6225-332MLB  value 3.3uH  [LPS6225]
L4  LPS6225-332MLB  value 3.3uH  [LPS6225]
R1  value 0  [0603]  (hidden comment: CRCW06030000Z0EA)
R2  value 0  [0603]  (hidden comment: CRCW06030000Z0EA)
R3  value 100k  [0603]  (hidden comment: CRCW0603100KFKEA)
R4  value 0  [0603]  (hidden comment: CRCW06030000Z0EA)
R5  ValueDisplayed: 4.99  [0603]  (hidden comment: CRCW06034R99FKEA)
R6  value 100k  [0603]  (hidden comment: CRCW0603100KFKEA)
R7  value 0  [0603]  (hidden comment: CRCW06030000Z0EA)
R8  DNP  [0603]
R9  ValueDisplayed: 50.5k  [0603]  (hidden comment: RT0603BRD0750K5L)
R10  value 100k  [0603]  (hidden comment: CRCW0603100KFKEA)
R11  ValueDisplayed: 10.0k  [0603]  (hidden comment: RT0603BRD0710KL)
R12  value 10k  [0603]  (hidden comment: RC0603JR-0710KL)
R13  value 4.99  [0805_HV]  (hidden comment: RC0805FR-074R99L)
R14  value 10k  [0603]  (hidden comment: RC0603JR-0710KL)
R15  value 49.9k  [0603]  (hidden comment: CRCW060349K9FKEA)
R16  ValueDisplayed: 6.65k  [0603]  (hidden comment: RT0603BRD076K65L)
R17  value 49.9k  [0603]  (hidden comment: CRCW060349K9FKEA)
R18  ValueDisplayed: 31.6k  [0603]  (hidden comment: RT0603BRD0731K6L)
R19  ValueDisplayed: 10.2k  [0603]  (hidden comment: RT0603BRD0710K2L)
R20  ValueDisplayed: 10.2k  [0603]  (hidden comment: RT0603BRD0710K2L)
TP1  5V  [Keystone5010]
TP2  SW  [Keystone5012]
TP3  5V  [Keystone1503-2]
TP4  GND  [Keystone5011]
TP5  GND  [Keystone1503-2]
TP6  6V  [Keystone1503-2]
TP7  GND  [Keystone1503-2]
TP8  5V_1  [Keystone1503-2]
TP9  5V_2  [Keystone1503-2]
TP10  GND  [Keystone1503-2]
TP11  GND  [Keystone1503-2]
TP12  1.32V  [Keystone1503-2]
TP13  5V_4  [Keystone1503-2]
TP14  5V_3  [Keystone1503-2]
TP15  3.3V  [Keystone1503-2]
TP16  3.3V  [Keystone5010]
TP17  GND  [Keystone1503-2]
TP18  GND  [Keystone1503-2]
TP19  5V_5  [Keystone1503-2]
TP20  5011  [Keystone5011]  (value not drawn)
TP21  5011  [Keystone5011]  (value not drawn)
TP22  GND  [Keystone1503-2]
U1  LM536025QPWP  PackageReference: PWP0016A  [PWP0016A_N]
U2  LM53600NQDSXRQ1  [DSX0010A]
U3  TPS7B4250QDBVRQ1  [DBV0005A_N]
U4  TPS7B4250QDBVRQ1  [DBV0005A_N]
U5  LM26420XSQ/NOPB  [SQB16A]
U6  TPS7B4250QDBVRQ1  [DBV0005A_N]
U7  TPS7B4250QDBVRQ1  [DBV0005A_N]
U8  TPS7B4253QPWPRQ1  [PWP0020D_N]

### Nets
5V_1: C17.1 TP8.1 U3.4(VOUT)
5V_2: C28.1 TP14.1 U7.4(VOUT)
5V_3: C19.1 TP9.1 U4.4(VOUT)
5V_4: C26.1 TP13.1 U6.4(VOUT)
5V_5: C36.1 TP19.1 U8.1(VOUT) U8.10(FB)
6V: C12.1 C13.1 C16.1 C18.1 C25.1 C27.1 C35.1 L2.2 R9.2 TP6.1 U3.3(VIN) U4.3(VIN) U6.3(VIN) U7.3(VIN) U8.20(VIN)
FB1: R9.1 R11.2 U2.4(FB)
GND: C1.2 C2.2 C3.2 C5.2(-) C6.2 C7.2 C8.2 C9.2 C10.2 C12.2 C13.2 C14.1 C15.1 C16.2 C17.2 C18.2 C19.2 C20.2 C21.2 C22.2 C23.2 C24.2 C25.2 C26.2 C27.2 C28.2 C29.2 C30.2 C31.2 C32.2 C33.2 C34.2 C35.2 C36.2 C37.2 CVCC1.1 R6.1 R8.1 R10.1 R11.1 R19.1 R20.1 TP4.1 TP5.1 TP7.1 TP10.1 TP11.1 TP17.1 TP18.1 TP20.1 TP21.1 TP22.1 U1.7(FPWM) U1.10(AGND) U1.15(PGND) U1.16(PGND) U1.17(PAD) U2.5(AGND) U2.10(GND) U2.11(PAD) U3.2(GND) U3.5(GND) U4.2(GND) U4.5(GND) U5.4(PGND1) U5.9(PGND2) U5.14(AGND) U5.17(DAP) U6.2(GND) U6.5(GND) U7.2(GND) U7.5(GND) U8.6(GND) U8.15(GND) U8.21(PAD)
Vcc: C10.1 R3.2 U1.4(VCC)
Vout: C5.1(+) C6.1 C7.1 C8.1 C11.1 C20.1 C21.1 C22.1 C23.1 C29.1 C30.1 C37.1 L1.2 R1.2 R7.2 R12.2 R13.2 R14.2 R15.1 R17.1 TP1.1 TP3.1 TP16.1 U3.1(ADJ/EN) U4.1(ADJ/EN) U5.1(VIND1) U5.2(VIND1) U5.11(VIND2) U5.12(VIND2) U6.1(ADJ/EN) U7.1(ADJ/EN) U8.11(ADJ) U8.19(EN)
Vs: C1.1 C2.1 C14.2 C15.2 R2.2 U1.12(VIN) U1.13(VIN) U2.7(EN) U2.8(VIN)  [also labelled Boost_Vout]
Bias: C3.1 R1.1 U1.5(BIAS)
FB: C11.2 R7.1 R8.2 U1.9(FB)
SW: L1.1 R4.2 R5.2 TP2.1 U1.1(SW) U1.2(SW)
Sync: R6.2 U1.6(SYNC)
Net1_1: 1.1 C31.1 C32.1 L3.1 R16.2 TP12.1
Net2_1: 2.1 C33.1 C34.1 L4.2 R18.2 TP15.1
NetC4_1: C4.1 R4.1
NetC4_2: C4.2 U1.3(CBOOT)
NetC9_1: C9.1 R5.1
NetC24_1: C24.1 R13.1 U5.15(VINC)
NetCBOOT1_1: CBOOT1.1 U2.2(BOOT)
NetCBOOT1_2: CBOOT1.2 L2.1 U2.1(SW)
NetCVCC1_2: CVCC1.2 U2.3(VCC)
NetL3_2: L3.2 U5.3(SW1)
NetL4_1: L4.1 U5.10(SW2)
NetR2_1: R2.1 U1.11(EN)
NetR3_1: R3.1 U1.8(~{RESET})
NetR10_2: R10.2 U2.9(SYNC/MODE)
NetR12_1: R12.1 U5.16(EN1)
NetR14_1: R14.1 U5.13(EN2)
NetR15_2: R15.2 U5.6(PG1)
NetR16_1: R16.1 R19.2 U5.5(FB1)
NetR17_2: R17.2 U5.7(PG2)
NetR18_1: R18.1 R20.2 U5.8(FB2)

Not connected (* = marked no-connect by the designer): U1 14(NC); U2 6(~{RESET}); U8 2(NC) 3(NC) 4(NC) 5(NC) 7(NC) 8(NC) 9(NC) 12(NC) 13(NC) 14(NC) 16(NC) 17(NC) 18(NC)

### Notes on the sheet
- 5V@2A
- (near C5) DNP
- 6V@650mA
- 1.32V@1A
- (near 2) 3.3V@1.0A
- (near U5) fsw = 2.2MHz

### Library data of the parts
1 2 TP1 TP16 = 5010: Test Point, Multipurpose, Red, TH; Manufacturer: Keystone; CompType: Test Point Loop; U/M: EA
C1 = GRM32ER71H106KA12L: as C42 on sheet TIDA-00745 REV1
C2 C3 = 06035C104KAT2A: CAP, CERM, 0.1uF, 50V, +/-10%, X7R, 0603; Manufacturer: AVX; Polarized: N; CompType: Capacitor; U/M: EA; Cap_F: 0.0000001; Tolerance_%: 10; Value1: Unknown; VDC_V: 50; TaMin_C: -55; TaMax_C: 125
C4 = C0603C474K8RACTU: CAP, CERM, 0.47uF, 10V, +/-10%, X7R, 0603; Manufacturer: Kemet; Polarized: N; CompType: Capacitor; U/M: EA; Cap_F: 0.00000047; Tolerance_%: 10; Value1: Unknown; TaMin_C: -55; TaMax_C: 125
C5 = APXC6R3ARA181MF60G: CAP, AL, 180uF, 6.3V, +/-20%, 0.022 ohm, SMD; Manufacturer: Nippon Chemi-Con; Polarized: Y; CompType: Capacitor; U/M: EA; Cap_F: 0.00018; Tolerance_%: 20; VDC_V: 6.3; ESR_Ohm: 0.022; IRMS_A: 2.58; TaMin_C: -55; TaMax_C: 105; Cap_Case: F60
C6-C8 = C3225X7R1C226M: CAP, CERM, 22uF, 16V, +/-20%, X7R, 1210; Manufacturer: TDK; Polarized: N; CompType: Capacitor; U/M: EA; Cap_F: 0.000022; Tolerance_%: 20; ESR_Ohm: 0.002; Value1: 0.002 ohm; VDC_V: 16; IRMS_A: 8.11; TaMin_C: -55; TaMax_C: 125
C9 = 06031C102JAT2A: CAP, CERM, 1000 pF, 100 V, +/- 5%, X7R, 0603; Manufacturer: AVX; Polarized: N; CompType: Capacitor; Value: 1000pF; U/M: EA; Cap_F: 0.000000001; Tolerance_%: 5; ESR_ohm: 0.276; Value1: 0.276 ohm; VDC_V: 100; Value2: 100V; TaMin_C: -55; TaMax_C: 125
C10 = GRM188R71A225KE15D: CAP, CERM, 2.2uF, 10V, +/-10%, X7R, 0603; Manufacturer: MuRata; Polarized: N; CompType: Capacitor; U/M: EA; Cap_F: 0.0000022; Tolerance_%: 10; ESR_Ohm: 0.009; Value1: 0.009 ohm; TaMin_C: -55; TaMax_C: 125
C11 = GRM188R71E333KA01D: CAP, CERM, 0.033uF, 25V, +/-10%, X7R, 0603; Manufacturer: MuRata; Polarized: N; CompType: Capacitor; U/M: EA; Cap_F: 0.000000033; Tolerance_%: 10; Value1: Unknown; VDC_V: 25; TaMin_C: -55; TaMax_C: 125
C12 C13 = C2012X7R1A106K125AC: CAP, CERM, 10 µF, 10 V, +/- 10%, X7R, 0805; Manufacturer: TDK; Polarized: N; CompType: Capacitor; Value: 10uF; U/M: EA; Cap_F: 0.00001; Tolerance_%: 10; Value1: Unknown; Value2: 10V; TaMin_C: -55; TaMax_C: 125; Cap_Case: 0805; AEC Category: Q200
C14 = GRM188R61C475KAAJ: CAP, CERM, 4.7 µF, 16 V, +/- 10%, X5R, 0603; Manufacturer: MuRata; Polarized: N; CompType: Capacitor; Value: 4.7uF; U/M: EA; Cap_F: 0.0000047; Tolerance_%: 10; Value1: Unknown; VDC_V: 16; Value2: 16V; TaMin_C: -55; TaMax_C: 85
C15 = 0603YC104JAT2A: CAP, CERM, 0.1 µF, 16 V, +/- 5%, X7R, 0603; Manufacturer: AVX; Polarized: N; CompType: Capacitor; Value: 0.1uF; U/M: EA; Cap_F: 0.0000001; Tolerance_%: 5; ESR_ohm: 0.039; Value1: 0.039 ohm; VDC_V: 16; Value2: 16V; TaMin_C: -55; TaMax_C: 125
C16 C18 C25 C27 C35 = GRM188R71A105KA61D: CAP, CERM, 1 µF, 10 V, +/- 10%, X7R, 0603; Manufacturer: MuRata; Polarized: N; CompType: Capacitor; Value: 1uF; U/M: EA; Cap_F: 0.000001; Tolerance_%: 10; ESR_ohm: 0.011; Value1: 0.011 ohm; Value2: 10V; TaMin_C: -55; TaMax_C: 125
C17 C19 C26 C28 C36 = GRM188R71A225KE15D: CAP, CERM, 2.2 µF, 10 V, +/- 10%, X7R, 0603; Manufacturer: MuRata; Polarized: N; CompType: Capacitor; Value: 2.2uF; U/M: EA; Cap_F: 0.0000022; Tolerance_%: 10; ESR_ohm: 0.009; Value1: 0.009 ohm; Value2: 10V; TaMin_C: -55; TaMax_C: 125
C20 C21 C29 C30 C37 = 0603ZC103KAT2A: CAP, CERM, 0.01 µF, 10 V, +/- 10%, X7R, 0603; Manufacturer: AVX; Polarized: N; CompType: Capacitor; Value: 0.01uF; U/M: EA; Cap_F: 0.00000001; Tolerance_%: 10; Value1: Unknown; Value2: 10V; TaMin_C: -55; TaMax_C: 125
C22 C23 = GRM31CR71A106KA01L: CAP, CERM, 10uF, 10V, +/-10%, X5R, 1206; Manufacturer: MuRata; Polarized: N; CompType: Capacitor; U/M: EA; Cap_F: 0.00001; Tolerance_%: 10; Value1: Unknown; TaMin_C: -55; TaMax_C: 85
C24 = GRM188R71A474KA61D: CAP, CERM, 0.47uF, 10V, +/-10%, X7R, 0603; Manufacturer: MuRata; Polarized: N; CompType: Capacitor; U/M: EA; Cap_F: 0.00000047; Tolerance_%: 10; Value1: Unknown; TaMin_C: -55; TaMax_C: 125
C31 C33 = GRM31CR60J476ME19L: CAP, CERM, 47uF, 6.3V, +/-20%, X5R, 1206; Manufacturer: MuRata; Polarized: N; CompType: Capacitor; U/M: EA; Cap_F: 0.000047; Tolerance_%: 20; ESR_Ohm: 0.003; Value1: 0.003 ohm; VDC_V: 6.3; TaMin_C: -55; TaMax_C: 85
C32 = GRM31CR71A226KE15L: CAP, CERM, 22uF, 10V, +/-10%, X7R, 1206; Manufacturer: MuRata; Polarized: N; CompType: Capacitor; U/M: EA; Cap_F: 0.000022; Tolerance_%: 10; Value1: Unknown; TaMin_C: -55; TaMax_C: 125
C34 = GRM31CR71A226KE15L: CAP, CERM, 22uF, 10V, +/-10%, X7R, 1206; Manufacturer: MuRata; Polarized: N; CompType: Capacitor; ValueDisplayed: DNP; U/M: EA; Cap_F: 0.000022; Tolerance_%: 10; Value1: Unknown; TaMin_C: -55; TaMax_C: 125
CBOOT1 = GRM188R71H104KA93D: as C56 on sheet TIDA-00745 REV1
CVCC1 = C1608X7R1C105K: CAP, CERM, 1uF, 16V, +/-10%, X7R, 0603; Manufacturer: TDK; Polarized: N; CompType: Capacitor; U/M: EA; Cap_F: 0.000001; Tolerance_%: 10; ESR_Ohm: 0.0057; Value1: 0.0057 ohm; VDC_V: 16; TaMin_C: -55; TaMax_C: 125
L1 = FDV0630-2R2M: Inductor, Shielded, Powdered Iron, 2.2uH, 5.3A, 0.021 ohm, SMD; Manufacturer: Toko; Ind_H: 2.2E-6; ValueDisplayed: 2.2µH; Imax_A: 5.3; Irms: 5.3A @ 40C rise; Isat: 6.4A @ 20% inductance drop; DCR_ohm: 0.021
L2 = MPI4040R3-4R7-R: Inductor, Shielded, ?, 4.7uH, 2.3A, 0.092 ohm, SMD; Manufacturer: Coiltronics; ValueDisplayed: 4.7µH; Ind_H: 4.7E-6; Imax_A: 2.3; Irms: 2.3A @ 40C rise; Isat: 4.8A @ 30% inductance drop; DCR_ohm: 0.092; U/M: EA; SymbolCreator: a0412235
L3 L4 = LPS6225-332MLB: Inductor, Shielded Drum Core, Ferrite, 3.3uH, 1.35A, 0.05 ohm, SMD; Manufacturer: Coilcraft; Ind_H: 3.3E-6; ValueDisplayed: 3.3µH; Imax_A: 1.35; Irms: 1.35A @ 40C rise; Isat: 3.6A @ 30% inductance drop; DCR_ohm: 0.05; U/M: EA
R1 R2 R4 = CRCW06030000Z0EA: as R27 on sheet TIDA-00745 REV1
R3 R6 R10 = CRCW0603100KFKEA: RES, 100k ohm, 1%, 0.1W, 0603; Manufacturer: Vishay-Dale; CompType: Resistor; Res_ohm: 100000; Tolerance_%: 1; Power_W: 0.1; VDC_V: 75; TempCo: 100 ppm/C; EIA_Code: E96; U/M: EA
R5 = CRCW06034R99FKEA: RES, 4.99, 1%, 0.1 W, 0603; Manufacturer: Vishay-Dale; CompType: Resistor; Value: 4.99; Value_Code: 4R99; Tolerance_%: 1; Power_W: 0.1; Value2: 0.1W; VDC_V: 75; TempCo: 100 ppm/C; EIA_Code: E96; U/M: EA
R7 = CRCW06030000Z0EA: RES, 0 ohm, 5%, 0.1W, 0603; Manufacturer: Vishay-Dale; CompType: Resistor; U/M: EA; Value_Code: 0000; Tolerance_%: 5; Power_W: 0.1; VDC_V: 75; TempCo: 200 ppm/C; EIA_Code: E24
R8 = CRCW06034K99FKEA: RES, 4.99k ohm, 1%, 0.1W, 0603; Manufacturer: Vishay-Dale; CompType: Resistor; U/M: EA; Res_ohm: 4990; Value_Code: 4k99; Tolerance_%: 1; Power_W: 0.1; VDC_V: 75; TempCo: 100 ppm/C; EIA_Code: E96
R9 = RT0603BRD0750K5L: RES, 50.5 k, 0.1%, 0.1 W, 0603; Manufacturer: Yageo America; CompType: Resistor; Value: 50.5k; Res_ohm: 50500; Value_Code: 50k5; Tolerance_%: 0.1; Value2: 0.1W; VDC_V: 75; TempCo: 25 ppm/C; EIA_Code: E192; U/M: EA
R11 = RT0603BRD0710KL: RES, 10.0 k, 0.1%, 0.1 W, 0603; Manufacturer: Yageo America; CompType: Resistor; Value: 10.0k; Res_ohm: 10000; Value_Code: 10k0; Tolerance_%: 0.1; Value2: 0.1W; VDC_V: 75; TempCo: 25 ppm/C; EIA_Code: E192; U/M: EA
R12 R14 = RC0603JR-0710KL: RES, 10k ohm, 5%, 0.1W, 0603; Manufacturer: Yageo America; CompType: Resistor; Res_ohm: 10000; Value_Code: 10k0; Tolerance_%: 5; Power_W: 0.1; VDC_V: 50; TempCo: 100 ppm/C; EIA_Code: E24; U/M: EA
R13 = RC0805FR-074R99L: RES, 4.99 ohm, 1%, 0.125W, 0805; Manufacturer: Yageo America; CompType: Resistor; Value_Code: 4R99; Tolerance_%: 1; Power_W: 0.125; VDC_V: 150; TempCo: 200 ppm/C; EIA_Code: E96; U/M: EA
R15 R17 = CRCW060349K9FKEA: RES, 49.9k ohm, 1%, 0.1W, 0603; Manufacturer: Vishay-Dale; CompType: Resistor; Res_ohm: 49900; Value_Code: 49k9; Tolerance_%: 1; Power_W: 0.1; VDC_V: 75; TempCo: 100 ppm/C; EIA_Code: E96; U/M: EA
R16 = RT0603BRD076K65L: RES, 6.65 k, 0.1%, 0.1 W, 0603; Manufacturer: Yageo America; CompType: Resistor; Value: 6.65k; Res_ohm: 6650; Value_Code: 6k65; Tolerance_%: 0.1; Value2: 0.1W; VDC_V: 75; TempCo: 25 ppm/C; EIA_Code: E192; U/M: EA
R18 = RT0603BRD0731K6L: RES, 31.6 k, 0.1%, 0.1 W, 0603; Manufacturer: Yageo America; CompType: Resistor; Value: 31.6k; Res_ohm: 31600; Value_Code: 31k6; Tolerance_%: 0.1; Value2: 0.1W; VDC_V: 75; TempCo: 25 ppm/C; EIA_Code: E192; U/M: EA
R19 R20 = RT0603BRD0710K2L: RES, 10.2 k, 0.1%, 0.1 W, 0603; Manufacturer: Yageo America; CompType: Resistor; Value: 10.2k; Res_ohm: 10200; Value_Code: 10k2; Tolerance_%: 0.1; Value2: 0.1W; VDC_V: 75; TempCo: 25 ppm/C; EIA_Code: E192; U/M: EA
TP2 = 5012: Test Point, Multipurpose, White, TH; Manufacturer: Keystone; CompType: Test Point Loop; U/M: EA
TP3 TP5-TP15 TP17-TP19 TP22 = 1503-2: as TP25 on sheet TIDA-00745 REV1
TP4 TP20 TP21 = 5011: Test Point, Multipurpose, Black, TH; Manufacturer: Keystone; CompType: Test Point Loop; U/M: EA
U1 = LM53603PWP: 6th GENERATION BUCK REGULATOR, PWP0016H; Alternate Manufacturer: None; Manufacturer: Texas Instruments; SymbolCreator: a0411947; CompType: IC; U/M: EA
U2 = LM53600NQDSXRQ1: Synchronous Buck Regulator for 650mA Space Constraint Applications, DSX0010A; Manufacturer: Texas Instruments; SymbolCreator: Altium; CompType: IC; U/M: EA
U3 U4 U6 U7 = TPS7B4250QDBVRQ1: Low Dropout Voltage Tracking LDO, DBV0005A; Manufacturer: Texas Instruments; SymbolCreator: a0411947; CompType: IC; U/M: EA
U5 = LM26420XSQ/NOPB: Dual 2.0A, High Frequency Synchronous Step-Down DC-DC Regulator, 16-pin LLP, Pb-Free; Manufacturer: National Semiconductor; PackageTopMarking: NS*UZXYTT*L26420X; PowerWise: Y; CompType: Switcher
U8 = TPS7B4253QPWPRQ1: 300mA Low Dropout Voltage Tracking LDO, PWP0020D; Manufacturer: Texas Instruments; SymbolCreator: a0799628; CompType: IC; U/M: EA

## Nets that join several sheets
GND: TIDA-00745 REV1 (32 pins), TIDA-00745_Buck REV1 (75 pins)
Vs: TIDA-00745 REV1 (16 pins), TIDA-00745_Buck REV1 (9 pins)

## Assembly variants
001: not fitted C5 FID1 FID2 FID3 R8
